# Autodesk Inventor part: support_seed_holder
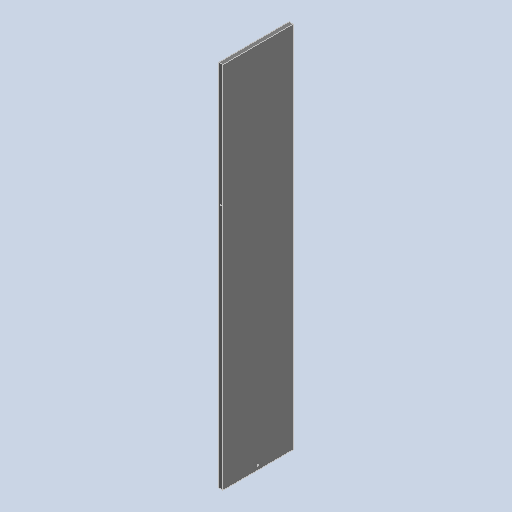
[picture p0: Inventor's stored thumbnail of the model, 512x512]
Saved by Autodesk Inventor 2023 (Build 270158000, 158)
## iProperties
Created: 2022-06
Part Number: support_seed_holder
Material: Polystyrene, Expanded
Document SubType Name: Modeling
Designer: prana_p9lsmih
Density: 0.05 g/cm^3
Appearance: Gray
Author: prana_p9lsmih
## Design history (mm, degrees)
sketch "Sketch1"
  geometry: L1 (0, 0)-(450, 0); L2 (450, 0)-(450, -86); L3 (450, -86)-(0, -86); L4 (0, -86)-(0, 0)
  constraints: 8 end point, 2 parallel, 1 horizontal, 1 perpendicular
  dimensions: "d0" = 450 distance of L2.end L3.end; "d1" = 86 distance of L1.end L2.end
extrude "Extrusion1" new body sketch "Sketch1" distance "d2" = 5; taper "d3" = 0 deg
sketch "Sketch2"
  geometry: L1 (0, 0)-(86, 0) reference; L2 (0, 450)-(0, 0) reference; 1 further point
  dimensions: "d4" = 5 distance from line of L1 point (43, 5); "d5" = 43 distance from line of L2 point (43, 5)
hole "Hole1" sketch "Sketch2" at (43, 5) diameter "d6" = 2; stored, may be unused: countersink angle "d10" = 90 deg, drill point angle "d12" = 118 deg; dims "d7" = 6, "d8" = 4, "d9" = 2, "d11" = 8
sketch "Sketch3"
  geometry: L1 (0, 450)-(5, 450) reference; L2 (5, 450)-(5, 0) reference; 2 further points
  dimensions: "d13" = 150 distance from line of L1 point (2.5, 300); "d14" = 2.5 distance from line of L2 point (2.5, 300)
hole "Hole2" sketch "Sketch3" at (2.5, 300) diameter "d15" = 1; stored, may be unused: countersink angle "d19" = 90 deg, drill point angle "d21" = 118 deg; dims "d16" = 6, "d17" = 4, "d18" = 2, "d20" = 8
body "Solid1"
